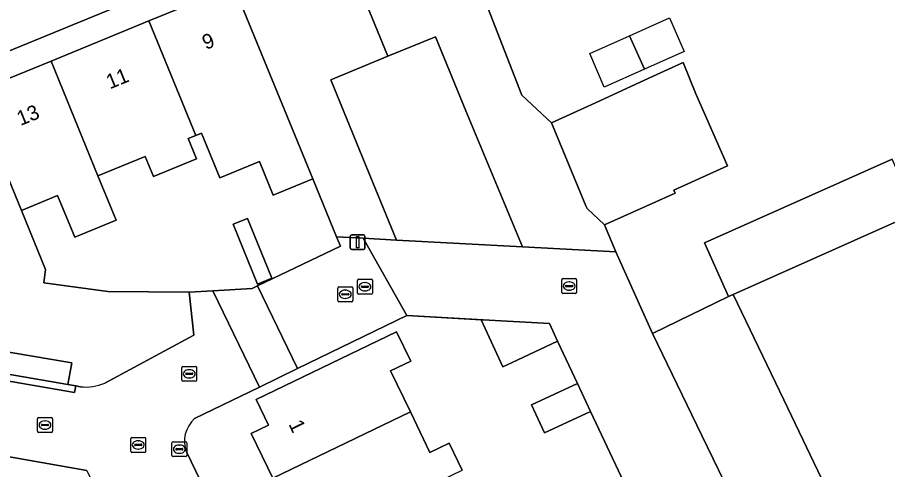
# Model space of a CAD drawing. Extents: x 159371 to 159986, y 382987 to 383597.
# Drawn here: x 159877.9 to 159936.7, y 383332 to 383362.5 of the extents above; entities that cross this region are included whole.
import ezdxf

# ---------------------------------------------------------------- set-up
doc = ezdxf.new("R2010")
doc.units = 0
for name, color, linetype in [('IMGEO_Brandkraan', 7, 'Continuous'), ('IMGEO_Erf', 7, 'Continuous'), ('IMGEO_Grasland_overig', 7, 'Continuous'), ('IMGEO_Kolk', 7, 'Continuous'), ('IMGEO_Lichtmast', 7, 'Continuous'), ('IMGEO_Muur', 7, 'Continuous'), ('IMGEO_Pand', 7, 'Continuous'), ('IMGEO_Pand_nummerreeks', 7, 'Continuous'), ('IMGEO_Pand_vergunning_verleend', 7, 'Continuous'), ('IMGEO_Rijbaan_lokaal_open', 7, 'Continuous'), ('IMGEO_Rioolput', 7, 'Continuous'), ('IMGEO_Voetpad_open', 7, 'Continuous')]:
    doc.layers.add(name, color=color, linetype=linetype)

msp = doc.modelspace()

# ---------------------------------------------------------------- linework, layer by layer
at = {"layer": 'IMGEO_Brandkraan'}
for p, q in [((159888.355, 383332.96), (159888.355, 383333.812)), ((159888.43, 383333.886), (159889.282, 383333.886)), ((159888.614, 383333.38), (159888.614, 383333.392)), ((159888.657, 383333.429), (159889.055, 383333.429)), ((159888.843, 383333.666), (159888.868, 383333.666)), ((159889.098, 383333.392), (159889.098, 383333.38)), ((159889.356, 383333.812), (159889.356, 383332.96)), ((159889.282, 383332.886), (159888.43, 383332.886)), ((159889.052, 383333.343), (159888.654, 383333.343)), ((159888.866, 383333.106), (159888.841, 383333.106))]:
    msp.add_line(p, q, dxfattribs=at)
for points in [[(159888.355, 383332.96), (159888.355, 383333.812)], [(159888.43, 383333.886), (159889.282, 383333.886)], [(159889.356, 383333.812), (159889.356, 383332.96)], [(159889.282, 383332.886), (159888.43, 383332.886)]]:
    msp.add_lwpolyline(points, dxfattribs=at)
for centre, radius, start, end in [((159888.432, 383333.81), 0.0765, 91.55205, 178.44795), ((159888.432, 383333.81), 0.0765, 91.55205, 178.44795), ((159888.654, 383333.389), 0.0403, 85.87752, 175.75265), ((159888.651, 383333.379), 0.0366, 178.93798, 274.71019), ((159889.055, 383333.386), 0.043, 264.86636, 352.45326), ((159889.059, 383333.391), 0.0386, 1.73085, 96.63898), ((159889.28, 383333.81), 0.0765, 1.55205, 88.44795), ((159889.28, 383333.81), 0.0765, 1.55205, 88.44795), ((159888.432, 383332.962), 0.0765, 181.55205, 268.44795), ((159888.432, 383332.962), 0.0765, 181.55205, 268.44795), ((159889.28, 383332.962), 0.0765, 271.55205, 358.44795), ((159889.28, 383332.962), 0.0765, 271.55205, 358.44795)]:
    msp.add_arc(centre, radius, start, end, dxfattribs=at)
for centre, major_axis, ratio, start_param, end_param in [((159888.842, 383333.386), (-0.387, 0.002), 0.722429, 4.712389, 7.853982), ((159888.867, 383333.386), (-0.39, 0.002), 0.717154, 1.570796, 4.712389)]:
    msp.add_ellipse(centre, major_axis=major_axis, ratio=ratio, start_param=start_param, end_param=end_param, dxfattribs=at)
at = {"layer": 'IMGEO_Erf'}
for points in [[(159908.377, 383366.545), (159911.987, 383357.288), (159913.983, 383355.409), (159916.962, 383356.776), (159920.557, 383358.426), (159922.87, 383359.487), (159923.738, 383357.367), (159925.88, 383352.502), (159922.252, 383350.875), (159922.345, 383350.671), (159917.563, 383348.528), (159918.322, 383346.711), (159920.796, 383341.192), (159925.938, 383343.687), (159924.319, 383347.317), (159936.986, 383352.966)], [(159938.605, 383349.337), (159926.254, 383343.828), (159929.674, 383336.71), (159932.987, 383329.817)], [(159919.046, 383330.776), (159916.626, 383335.939), (159913.512, 383334.479), (159912.625, 383336.371), (159915.739, 383337.831), (159914.401, 383340.683), (159911.288, 383339.223), (159910.692, 383338.944), (159909.234, 383342.12), (159904.224, 383342.402), (159896.845, 383338.825), (159894.261, 383337.572), (159889.883, 383335.45)], [(159895.179, 383331.419), (159893.717, 383334.45), (159894.885, 383335.014), (159894.048, 383336.748), (159903.52, 383341.317), (159904.477, 383339.333), (159903.115, 383338.676), (159904.455, 383335.898), (159905.777, 383333.158), (159907.083, 383333.789), (159907.959, 383331.973)], [(159889.33, 383333.201), (159894.844, 383321.788), (159865.016, 383294.523), (159865.824, 383292.999), (159871.408, 383282.46), (159868.331, 383280.801), (159862.618, 383291.479), (159858.55, 383289.55), (159859.397, 383287.763), (159853.263, 383284.853), (159852.415, 383286.641), (159846.218, 383283.702), (159839.901, 383280.705)]]:
    msp.add_lwpolyline(points, dxfattribs=at)
for points in [[(159902.941, 383359.909), (159899.084, 383358.329), (159901.256, 383353.027), (159903.519, 383347.504), (159912.029, 383347.048), (159908.195, 383356.229), (159906.149, 383361.223)], [(159897.864, 383351.637), (159895.192, 383350.542), (159894.262, 383352.81), (159891.587, 383351.714), (159890.356, 383354.719), (159889.969, 383354.561), (159889.459, 383354.352), (159890.02, 383352.984), (159887.11, 383351.792), (159886.555, 383353.148), (159883.363, 383351.84), (159884.593, 383348.837), (159881.789, 383347.688), (159880.635, 383350.504), (159878.193, 383349.504), (159879.828, 383345.513), (159879.706, 383344.612), (159884.017, 383344.028), (159889.525, 383343.991), (159891.108, 383344.079), (159893.774, 383344.226), (159894.14, 383344.402), (159899.734, 383347.089), (159899.471, 383347.721)], [(159892.483, 383348.572), (159893.449, 383348.968), (159895.104, 383344.929), (159894.138, 383344.533)]]:
    msp.add_lwpolyline(points, close=True, dxfattribs=at)
msp.add_arc((159891.247, 383333.922), 2.048, 131.75185, 200.61967, dxfattribs=at)
at = {"layer": 'IMGEO_Grasland_overig'}
msp.add_lwpolyline([(159869.846, 383339.731), (159881.331, 383337.761), (159881.598, 383339.216), (159869.208, 383341.301)], close=True, dxfattribs=at)
at = {"layer": 'IMGEO_Kolk'}
for p, q in [((159914.68, 383343.972), (159914.68, 383344.824)), ((159914.755, 383344.898), (159915.607, 383344.898)), ((159915.168, 383344.678), (159915.193, 383344.678)), ((159915.681, 383344.824), (159915.681, 383343.972)), ((159899.559, 383343.414), (159899.559, 383344.266)), ((159899.634, 383344.34), (159900.486, 383344.34)), ((159900.047, 383344.12), (159900.072, 383344.12)), ((159900.56, 383344.266), (159900.56, 383343.414)), ((159914.939, 383344.392), (159914.939, 383344.404)), ((159915.377, 383344.355), (159914.979, 383344.355)), ((159914.982, 383344.441), (159915.38, 383344.441)), ((159915.191, 383344.118), (159915.166, 383344.118)), ((159915.423, 383344.404), (159915.423, 383344.392)), ((159899.818, 383343.834), (159899.818, 383343.846)), ((159900.256, 383343.797), (159899.858, 383343.797)), ((159899.861, 383343.883), (159900.259, 383343.883)), ((159900.07, 383343.56), (159900.045, 383343.56)), ((159900.302, 383343.846), (159900.302, 383343.834)), ((159915.607, 383343.898), (159914.755, 383343.898)), ((159900.486, 383343.34), (159899.634, 383343.34)), ((159889.025, 383338.048), (159889.025, 383338.9)), ((159889.1, 383338.974), (159889.952, 383338.974)), ((159889.513, 383338.754), (159889.538, 383338.754)), ((159890.026, 383338.9), (159890.026, 383338.048)), ((159889.284, 383338.468), (159889.284, 383338.48)), ((159889.722, 383338.431), (159889.324, 383338.431)), ((159889.327, 383338.517), (159889.725, 383338.517)), ((159889.536, 383338.194), (159889.511, 383338.194)), ((159889.768, 383338.48), (159889.768, 383338.468)), ((159889.952, 383337.974), (159889.1, 383337.974)), ((159879.283, 383334.592), (159879.283, 383335.444)), ((159879.358, 383335.518), (159880.21, 383335.518)), ((159879.771, 383335.298), (159879.796, 383335.298)), ((159880.284, 383335.444), (159880.284, 383334.592)), ((159879.542, 383335.012), (159879.542, 383335.024)), ((159879.98, 383334.975), (159879.582, 383334.975)), ((159879.585, 383335.061), (159879.983, 383335.061)), ((159879.794, 383334.738), (159879.769, 383334.738)), ((159880.026, 383335.024), (159880.026, 383335.012)), ((159880.21, 383334.518), (159879.358, 383334.518))]:
    msp.add_line(p, q, dxfattribs=at)
for points in [[(159914.68, 383343.972), (159914.68, 383344.824)], [(159914.755, 383344.898), (159915.607, 383344.898)], [(159915.681, 383344.824), (159915.681, 383343.972)], [(159899.559, 383343.414), (159899.559, 383344.266)], [(159899.634, 383344.34), (159900.486, 383344.34)], [(159900.56, 383344.266), (159900.56, 383343.414)], [(159915.607, 383343.898), (159914.755, 383343.898)], [(159900.486, 383343.34), (159899.634, 383343.34)], [(159889.025, 383338.048), (159889.025, 383338.9)], [(159889.1, 383338.974), (159889.952, 383338.974)], [(159890.026, 383338.9), (159890.026, 383338.048)], [(159889.952, 383337.974), (159889.1, 383337.974)], [(159879.283, 383334.592), (159879.283, 383335.444)], [(159879.358, 383335.518), (159880.21, 383335.518)], [(159880.284, 383335.444), (159880.284, 383334.592)], [(159880.21, 383334.518), (159879.358, 383334.518)]]:
    msp.add_lwpolyline(points, dxfattribs=at)
for centre, radius, start, end in [((159914.757, 383344.822), 0.0765, 91.55205, 178.44795), ((159914.757, 383344.822), 0.0765, 91.55205, 178.44795), ((159915.605, 383344.822), 0.0765, 1.55205, 88.44795), ((159915.605, 383344.822), 0.0765, 1.55205, 88.44795), ((159899.636, 383344.264), 0.0765, 91.55205, 178.44795), ((159899.636, 383344.264), 0.0765, 91.55205, 178.44795), ((159900.484, 383344.264), 0.0765, 1.55205, 88.44795), ((159900.484, 383344.264), 0.0765, 1.55205, 88.44795), ((159914.757, 383343.974), 0.0765, 181.55205, 268.44795), ((159914.757, 383343.974), 0.0765, 181.55205, 268.44795), ((159914.979, 383344.401), 0.0403, 85.87752, 175.75265), ((159914.976, 383344.391), 0.0366, 178.93798, 274.71019), ((159915.38, 383344.398), 0.043, 264.86636, 352.45326), ((159915.384, 383344.403), 0.0386, 1.73085, 96.63898), ((159915.605, 383343.974), 0.0765, 271.55205, 358.44795), ((159915.605, 383343.974), 0.0765, 271.55205, 358.44795), ((159899.636, 383343.416), 0.0765, 181.55205, 268.44795), ((159899.636, 383343.416), 0.0765, 181.55205, 268.44795), ((159899.858, 383343.843), 0.0403, 85.87752, 175.75265), ((159899.855, 383343.833), 0.0366, 178.93798, 274.71019), ((159900.259, 383343.84), 0.043, 264.86636, 352.45326), ((159900.263, 383343.845), 0.0386, 1.73085, 96.63898), ((159900.484, 383343.416), 0.0765, 271.55205, 358.44795), ((159900.484, 383343.416), 0.0765, 271.55205, 358.44795), ((159889.102, 383338.898), 0.0765, 91.55205, 178.44795), ((159889.102, 383338.898), 0.0765, 91.55205, 178.44795), ((159889.95, 383338.898), 0.0765, 1.55205, 88.44795), ((159889.95, 383338.898), 0.0765, 1.55205, 88.44795), ((159889.324, 383338.477), 0.0403, 85.87752, 175.75265), ((159889.321, 383338.467), 0.0366, 178.93798, 274.71019), ((159889.725, 383338.474), 0.043, 264.86636, 352.45326), ((159889.729, 383338.479), 0.0386, 1.73085, 96.63898), ((159889.102, 383338.05), 0.0765, 181.55205, 268.44795), ((159889.102, 383338.05), 0.0765, 181.55205, 268.44795), ((159889.95, 383338.05), 0.0765, 271.55205, 358.44795), ((159889.95, 383338.05), 0.0765, 271.55205, 358.44795), ((159879.36, 383335.442), 0.0765, 91.55205, 178.44795), ((159879.36, 383335.442), 0.0765, 91.55205, 178.44795), ((159880.208, 383335.442), 0.0765, 1.55205, 88.44795), ((159880.208, 383335.442), 0.0765, 1.55205, 88.44795), ((159879.36, 383334.594), 0.0765, 181.55205, 268.44795), ((159879.36, 383334.594), 0.0765, 181.55205, 268.44795), ((159879.582, 383335.021), 0.0403, 85.87752, 175.75265), ((159879.579, 383335.011), 0.0366, 178.93798, 274.71019), ((159879.983, 383335.018), 0.043, 264.86636, 352.45326), ((159879.987, 383335.023), 0.0386, 1.73085, 96.63898), ((159880.208, 383334.594), 0.0765, 271.55205, 358.44795), ((159880.208, 383334.594), 0.0765, 271.55205, 358.44795)]:
    msp.add_arc(centre, radius, start, end, dxfattribs=at)
for centre, major_axis, ratio, start_param, end_param in [((159915.167, 383344.398), (-0.387, 0.002), 0.722429, 4.712389, 7.853982), ((159915.192, 383344.398), (-0.39, 0.002), 0.717154, 1.570796, 4.712389), ((159900.046, 383343.84), (-0.387, 0.002), 0.722429, 4.712389, 7.853982), ((159900.071, 383343.84), (-0.39, 0.002), 0.717154, 1.570796, 4.712389), ((159889.512, 383338.474), (-0.387, 0.002), 0.722429, 4.712389, 7.853982), ((159889.537, 383338.474), (-0.39, 0.002), 0.717154, 1.570796, 4.712389), ((159879.77, 383335.018), (-0.387, 0.002), 0.722429, 4.712389, 7.853982), ((159879.795, 383335.018), (-0.39, 0.002), 0.717154, 1.570796, 4.712389)]:
    msp.add_ellipse(centre, major_axis=major_axis, ratio=ratio, start_param=start_param, end_param=end_param, dxfattribs=at)
at = {"layer": 'IMGEO_Lichtmast'}
for p, q in [((159900.399, 383346.962), (159900.399, 383347.762)), ((159900.399, 383347.762), (159900.399, 383346.962)), ((159900.499, 383347.862), (159901.289, 383347.862)), ((159901.289, 383347.862), (159900.499, 383347.862)), ((159901.389, 383347.762), (159901.389, 383346.962)), ((159901.389, 383346.962), (159901.389, 383347.762)), ((159901.289, 383346.862), (159900.499, 383346.862)), ((159900.499, 383346.862), (159901.289, 383346.862))]:
    msp.add_line(p, q, dxfattribs=at)
msp.add_lwpolyline([(159900.819, 383347.737), (159900.969, 383347.737), (159900.969, 383346.987), (159900.819, 383346.987), (159900.819, 383347.737)], dxfattribs=at)
for centre, start, end in [((159900.499, 383347.762), 90, 180), ((159900.499, 383347.762), 90, 180), ((159901.289, 383347.762), 0, 90), ((159901.289, 383347.762), 360, 90), ((159900.499, 383346.962), 180, 270), ((159900.499, 383346.962), 180, 270), ((159901.289, 383346.962), 270, 0), ((159901.289, 383346.962), 270, 0)]:
    msp.add_arc(centre, 0.1, start, end, dxfattribs=at)
at = {"layer": 'IMGEO_Muur'}
for points in [[(159891.108, 383344.079), (159889.525, 383343.991)], [(159894.14, 383344.402), (159893.774, 383344.226), (159891.108, 383344.079)], [(159909.378, 383342.112), (159904.224, 383342.402)], [(159914.401, 383340.683), (159915.739, 383337.831)], [(159916.626, 383335.939), (159919.046, 383330.776)]]:
    msp.add_lwpolyline(points, dxfattribs=at)
at = {"layer": 'IMGEO_Pand'}
for points in [[(159908.377, 383366.545), (159906.767, 383370.475), (159899.783, 383367.614), (159902.941, 383359.909), (159906.149, 383361.223), (159908.195, 383356.229), (159912.029, 383347.048), (159918.322, 383346.711), (159917.563, 383348.528), (159916.399, 383349.622), (159916.315, 383349.823), (159913.983, 383355.409), (159911.987, 383357.288)], [(159902.941, 383359.909), (159899.783, 383367.614), (159892.526, 383364.641), (159897.864, 383351.637), (159899.471, 383347.721), (159901.277, 383347.624), (159903.519, 383347.504), (159901.256, 383353.027), (159899.084, 383358.329)], [(159892.526, 383364.641), (159886.8, 383362.295), (159889.969, 383354.561), (159890.356, 383354.719), (159891.587, 383351.714), (159894.262, 383352.81), (159895.192, 383350.542), (159897.864, 383351.637)], [(159883.363, 383351.84), (159886.555, 383353.148), (159887.11, 383351.792), (159890.02, 383352.984), (159889.459, 383354.352), (159889.969, 383354.561), (159886.8, 383362.295), (159880.193, 383359.588)], [(159874.945, 383357.438), (159878.193, 383349.504), (159880.635, 383350.504), (159881.789, 383347.688), (159884.593, 383348.837), (159883.363, 383351.84), (159880.193, 383359.588)], [(159923.738, 383357.367), (159922.87, 383359.487), (159920.557, 383358.426), (159916.962, 383356.776), (159913.983, 383355.409), (159916.315, 383349.823), (159916.399, 383349.622), (159917.563, 383348.528), (159922.345, 383350.671), (159922.252, 383350.875), (159925.88, 383352.502)], [(159924.319, 383347.317), (159925.938, 383343.687), (159926.249, 383343.838), (159926.254, 383343.828), (159938.605, 383349.337), (159936.986, 383352.966)], [(159892.483, 383348.572), (159894.138, 383344.533), (159895.104, 383344.929), (159893.449, 383348.968)], [(159929.674, 383336.71), (159926.254, 383343.828), (159926.249, 383343.838), (159925.938, 383343.687), (159920.796, 383341.192), (159924.134, 383334.314), (159927.534, 383327.309), (159932.987, 383329.817)], [(159913.85, 383341.86), (159909.378, 383342.112), (159909.234, 383342.12), (159910.692, 383338.944), (159911.288, 383339.223), (159914.401, 383340.683)], [(159895.179, 383331.419), (159904.455, 383335.898), (159903.115, 383338.676), (159904.477, 383339.333), (159903.52, 383341.317), (159894.048, 383336.748), (159894.885, 383335.014), (159893.717, 383334.45)], [(159916.626, 383335.939), (159915.739, 383337.831), (159912.625, 383336.371), (159913.512, 383334.479)], [(159906.594, 383331.314), (159907.959, 383331.973), (159907.083, 383333.789), (159905.777, 383333.158), (159904.455, 383335.898), (159895.179, 383331.419), (159896.62, 383328.433), (159897.782, 383328.993), (159898.466, 383327.574), (159897.298, 383327.01), (159897.369, 383326.862)]]:
    msp.add_lwpolyline(points, close=True, dxfattribs=at)
msp.add_lwpolyline([(159883.83, 383337.841), (159889.843, 383341.082), (159889.525, 383343.991), (159884.017, 383344.028), (159879.706, 383344.612), (159879.828, 383345.513), (159878.193, 383349.504), (159874.945, 383357.438), (159866.522, 383353.987), (159865.29, 383351.045), (159869.208, 383341.301), (159881.598, 383339.216), (159881.331, 383337.761), (159881.859, 383337.661), (159882.174, 383337.602)], dxfattribs=at)
msp.add_arc((159882.532, 383340.981), 3.398, 263.96119, 292.46367, dxfattribs=at)
at = {"layer": 'IMGEO_Pand_vergunning_verleend'}
for points in [[(159919.251, 383361.295), (159921.951, 383362.492), (159922.953, 383360.229), (159920.259, 383359.043)], [(159916.574, 383360.097), (159919.251, 383361.295), (159920.259, 383359.043), (159917.547, 383357.829)]]:
    msp.add_lwpolyline(points, close=True, dxfattribs=at)
at = {"layer": 'IMGEO_Rijbaan_lokaal_open'}
for points in [[(159855.412, 383349.492), (159862.546, 383354.138), (159873.236, 383358.594), (159895.93, 383367.9), (159894.206, 383372.109), (159874.665, 383364.08), (159870.989, 383362.556), (159852.647, 383355.016), (159854.94, 383349.623), (159855.086, 383349.291)], [(159927.534, 383327.309), (159924.134, 383334.314), (159920.796, 383341.192), (159918.322, 383346.711), (159912.029, 383347.048), (159903.519, 383347.504), (159901.277, 383347.624), (159904.224, 383342.402), (159909.234, 383342.12), (159909.378, 383342.112), (159913.85, 383341.86), (159914.401, 383340.683), (159915.739, 383337.831), (159916.626, 383335.939), (159919.046, 383330.776)], [(159889.883, 383335.45), (159894.261, 383337.572), (159891.108, 383344.079), (159889.525, 383343.991), (159889.843, 383341.082), (159883.83, 383337.841)], [(159882.174, 383337.602), (159881.859, 383337.661), (159881.768, 383337.219), (159869.905, 383339.262), (159869.058, 383334.343), (159882.613, 383331.946), (159883.082, 383330.981), (159887.034, 383322.854), (159887.954, 383320.962), (159882.61, 383316.018), (159870.056, 383304.404), (159868.657, 383305.873), (159867.427, 383304.743), (159864.853, 383302.387), (159862.366, 383300.11), (159865.016, 383294.523), (159894.844, 383321.788), (159889.33, 383333.201)]]:
    msp.add_lwpolyline(points, dxfattribs=at)
for points in [[(159901.277, 383347.624), (159899.471, 383347.721), (159899.734, 383347.089), (159894.14, 383344.402), (159896.845, 383338.825), (159904.224, 383342.402)], [(159894.14, 383344.402), (159893.774, 383344.226), (159891.108, 383344.079), (159894.261, 383337.572), (159896.845, 383338.825)]]:
    msp.add_lwpolyline(points, close=True, dxfattribs=at)
for centre, radius, start, end in [((159882.532, 383340.981), 3.398, 263.96119, 292.46367), ((159891.247, 383333.922), 2.048, 131.75185, 200.61967)]:
    msp.add_arc(centre, radius, start, end, dxfattribs=at)
at = {"layer": 'IMGEO_Rioolput'}
for p, q in [((159900.887, 383343.927), (159900.887, 383344.779)), ((159900.962, 383344.853), (159901.814, 383344.853)), ((159901.375, 383344.633), (159901.4, 383344.633)), ((159901.888, 383344.779), (159901.888, 383343.927)), ((159901.146, 383344.347), (159901.146, 383344.359)), ((159901.584, 383344.31), (159901.186, 383344.31)), ((159901.189, 383344.396), (159901.587, 383344.396)), ((159901.398, 383344.073), (159901.373, 383344.073)), ((159901.63, 383344.359), (159901.63, 383344.347)), ((159901.814, 383343.853), (159900.962, 383343.853)), ((159885.581, 383333.247), (159885.581, 383334.099)), ((159885.656, 383334.173), (159886.508, 383334.173)), ((159886.069, 383333.953), (159886.094, 383333.953)), ((159886.582, 383334.099), (159886.582, 383333.247)), ((159885.84, 383333.667), (159885.84, 383333.679)), ((159886.278, 383333.63), (159885.88, 383333.63)), ((159885.883, 383333.716), (159886.281, 383333.716)), ((159886.092, 383333.393), (159886.067, 383333.393)), ((159886.324, 383333.679), (159886.324, 383333.667)), ((159886.508, 383333.173), (159885.656, 383333.173))]:
    msp.add_line(p, q, dxfattribs=at)
for points in [[(159900.887, 383343.927), (159900.887, 383344.779)], [(159900.962, 383344.853), (159901.814, 383344.853)], [(159901.888, 383344.779), (159901.888, 383343.927)], [(159901.814, 383343.853), (159900.962, 383343.853)], [(159885.581, 383333.247), (159885.581, 383334.099)], [(159885.656, 383334.173), (159886.508, 383334.173)], [(159886.582, 383334.099), (159886.582, 383333.247)], [(159886.508, 383333.173), (159885.656, 383333.173)]]:
    msp.add_lwpolyline(points, dxfattribs=at)
for centre, radius, start, end in [((159900.964, 383344.777), 0.0765, 91.55205, 178.44795), ((159900.964, 383344.777), 0.0765, 91.55205, 178.44795), ((159901.812, 383344.777), 0.0765, 1.55205, 88.44795), ((159901.812, 383344.777), 0.0765, 1.55205, 88.44795), ((159901.186, 383344.356), 0.0403, 85.87752, 175.75265), ((159901.183, 383344.346), 0.0366, 178.93798, 274.71019), ((159901.587, 383344.353), 0.043, 264.86636, 352.45326), ((159901.591, 383344.358), 0.0386, 1.73085, 96.63898), ((159900.964, 383343.929), 0.0765, 181.55205, 268.44795), ((159900.964, 383343.929), 0.0765, 181.55205, 268.44795), ((159901.812, 383343.929), 0.0765, 271.55205, 358.44795), ((159901.812, 383343.929), 0.0765, 271.55205, 358.44795), ((159885.658, 383334.097), 0.0765, 91.55205, 178.44795), ((159885.658, 383334.097), 0.0765, 91.55205, 178.44795), ((159886.506, 383334.097), 0.0765, 1.55205, 88.44795), ((159886.506, 383334.097), 0.0765, 1.55205, 88.44795), ((159885.88, 383333.676), 0.0403, 85.87752, 175.75265), ((159885.877, 383333.666), 0.0366, 178.93798, 274.71019), ((159886.281, 383333.673), 0.043, 264.86636, 352.45326), ((159886.285, 383333.678), 0.0386, 1.73085, 96.63898), ((159885.658, 383333.249), 0.0765, 181.55205, 268.44795), ((159885.658, 383333.249), 0.0765, 181.55205, 268.44795), ((159886.506, 383333.249), 0.0765, 271.55205, 358.44795), ((159886.506, 383333.249), 0.0765, 271.55205, 358.44795)]:
    msp.add_arc(centre, radius, start, end, dxfattribs=at)
for centre, major_axis, ratio, start_param, end_param in [((159901.374, 383344.353), (-0.387, 0.002), 0.722429, 4.712389, 7.853982), ((159901.399, 383344.353), (-0.39, 0.002), 0.717154, 1.570796, 4.712389), ((159886.068, 383333.673), (-0.387, 0.002), 0.722429, 4.712389, 7.853982), ((159886.093, 383333.673), (-0.39, 0.002), 0.717154, 1.570796, 4.712389)]:
    msp.add_ellipse(centre, major_axis=major_axis, ratio=ratio, start_param=start_param, end_param=end_param, dxfattribs=at)
at = {"layer": 'IMGEO_Voetpad_open'}
for points in [[(159869.905, 383339.262), (159881.768, 383337.219), (159881.859, 383337.661), (159881.331, 383337.761), (159869.846, 383339.731), (159869.208, 383341.301), (159865.29, 383351.045), (159866.522, 383353.987), (159874.945, 383357.438), (159880.193, 383359.588), (159886.8, 383362.295), (159892.526, 383364.641), (159899.783, 383367.614), (159906.767, 383370.475), (159906.023, 383372.039), (159898.484, 383368.948), (159895.93, 383367.9), (159873.236, 383358.594), (159862.546, 383354.138), (159855.412, 383349.492)], [(159882.613, 383331.946), (159869.058, 383334.343), (159867.737, 383334.577), (159867.665, 383334.127)]]:
    msp.add_lwpolyline(points, dxfattribs=at)

# ---------------------------------------------------------------- texts
at = {"layer": 'IMGEO_Pand_nummerreeks'}
for s, rotation, p in [('9', 22.2766, (159890.651, 383360.328)), ('11', 22.27974, (159884.165, 383357.671)), ('13', 22.27793, (159878.131, 383355.199)), ('1', 295.72658, (159896.208, 383335.082))]:
    msp.add_text(s, height=1, rotation=rotation, dxfattribs=at).set_placement(p)

doc.saveas('drawing.dxf')
